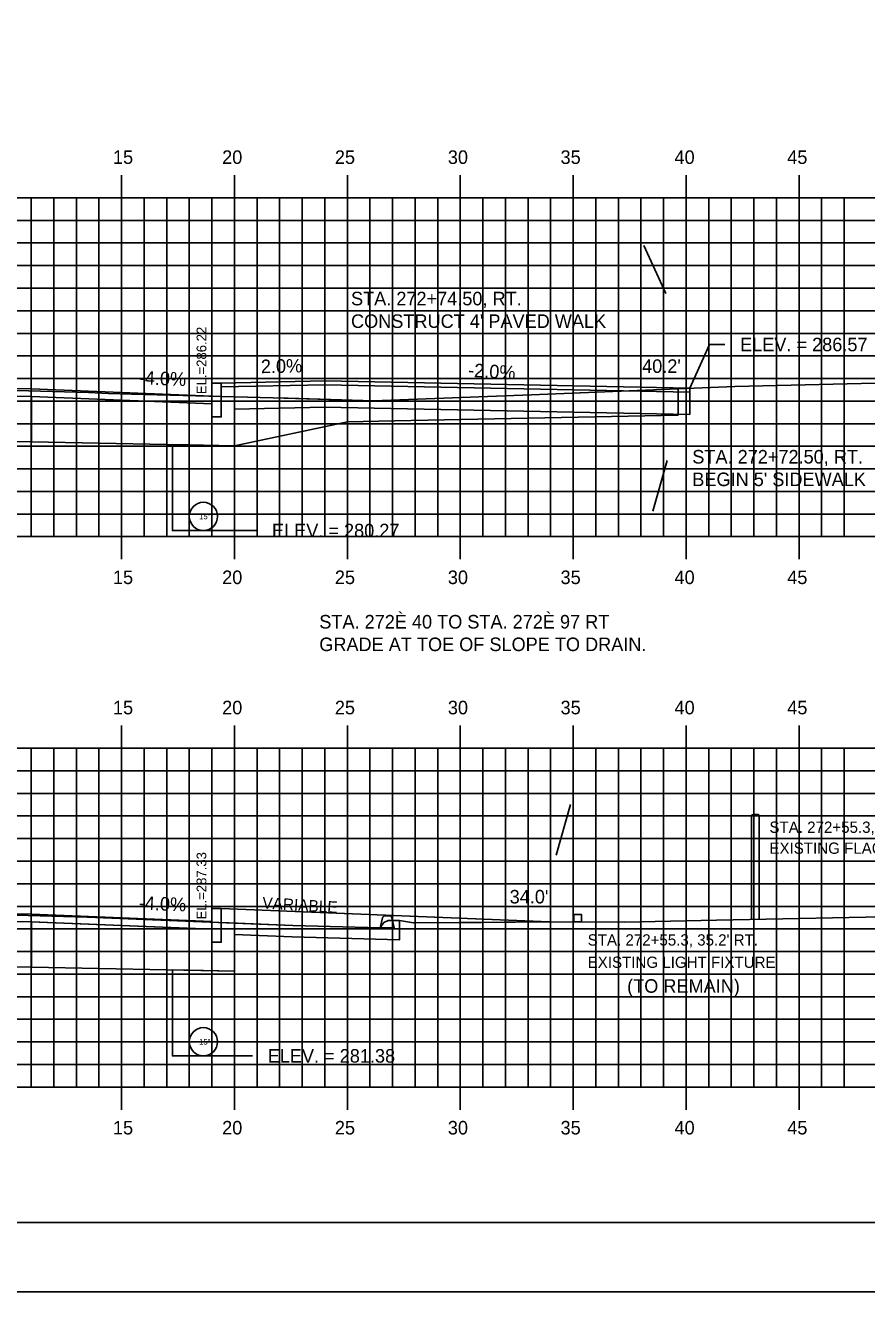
# Model space of a CAD drawing. Extents: x 852672 to 852842, y 366268 to 366378.
# Drawn here: x 852765.8 to 852803.1, y 366268.2 to 366324.2 of the extents above; entities that cross this region are included whole.
import ezdxf

# ---------------------------------------------------------------- set-up
doc = ezdxf.new("R2010")
doc.units = 0
for name, color, linetype in [('ANNOTATION', 7, 'Continuous'), ('BORDER', 7, 'Continuous'), ('D_Curb_Type1_Rt', 7, 'Continuous'), ('D_Drainage_Text', 7, 'Continuous'), ('D_Roadway_Edge_Shoulder', 7, 'Continuous'), ('D_Roadway_FinishedGrade', 7, 'Continuous'), ('D_Roadway_Sidewalks_Paved', 7, 'Continuous'), ('D_Roadway_SubGrade', 7, 'Continuous'), ('D_Text_Monospaced', 7, 'Continuous'), ('D_Text_Standard', 7, 'Continuous'), ('H_V ANNOTATION', 7, 'Continuous'), ('JUNK COM EXC', 7, 'Continuous'), ('JUNK FILL', 7, 'Continuous'), ('junk grubnfill', 7, 'Continuous'), ('junk strct exc', 7, 'Continuous'), ('MAJOR', 7, 'Continuous'), ('MINOR', 7, 'Continuous'), ('PDRAIN', 7, 'Continuous'), ('PLOT BOUNDARY', 7, 'Continuous'), ('S_Curb_Type_3', 7, 'Continuous'), ('S_Roadway_Centerline', 7, 'Continuous'), ('S_Utilities_Pole_Joint', 7, 'Continuous')]:
    doc.layers.add(name, color=color, linetype=linetype)

msp = doc.modelspace()

# ---------------------------------------------------------------- linework, layer by layer
at = {"layer": 'ANNOTATION'}
for p, q in [((852794.196, 366312.37), (852793.228, 366314.496)), ((852793.617, 366302.727), (852794.26, 366304.973)), ((852789.339, 366287.505), (852789.982, 366289.751))]:
    msp.add_line(p, q, dxfattribs=at)
at = {"layer": 'BORDER'}
msp.add_line((852680.097, 366271.236), (852840.097, 366271.236), dxfattribs=at)
at = {"layer": 'D_Curb_Type1_Rt'}
for points in [[(852774.513, 366308.402), (852774.513, 366306.902), (852774.096, 366306.902), (852774.096, 366308.402)], [(852774.513, 366285.146), (852774.513, 366283.646), (852774.096, 366283.646), (852774.096, 366285.146)]]:
    msp.add_lwpolyline(points, close=True, dxfattribs=at)
at = {"layer": 'D_Roadway_Edge_Shoulder'}
for p, q in [((852766.096, 366308.139), (852774.096, 366307.819)), ((852766.096, 366284.883), (852774.096, 366284.563)), ((852766.083, 366284.55), (852774.096, 366284.23))]:
    msp.add_line(p, q, dxfattribs=at)
for points in [[(852744.096, 366308.139), (852755.096, 366308.359), (852766.096, 366308.139)], [(852744.096, 366284.883), (852755.096, 366285.103), (852766.096, 366284.883)]]:
    msp.add_lwpolyline(points, dxfattribs=at)
at = {"layer": 'D_Roadway_FinishedGrade'}
msp.add_lwpolyline([(852774.513, 366285.146), (852789.054, 366284.547)], dxfattribs=at)
at = {"layer": 'D_Roadway_Sidewalks_Paved'}
for p, q in [((852779.101, 366308.494), (852795.259, 366308.171)), ((852779.101, 366308.327), (852795.259, 366308.004))]:
    msp.add_line(p, q, dxfattribs=at)
msp.add_lwpolyline([(852774.513, 366308.402), (852779.101, 366308.494), (852779.101, 366308.328), (852774.513, 366308.236)], close=True, dxfattribs=at)
at = {"layer": 'D_Roadway_SubGrade'}
for p, q in [((852795.259, 366308.171), (852795.259, 366307.004)), ((852774.096, 366307.486), (852774.096, 366307.819)), ((852779.078, 366307.327), (852795.259, 366307.004)), ((852782.399, 366284.612), (852782.399, 366283.753))]:
    msp.add_line(p, q, dxfattribs=at)
for points in [[(852744.103, 366305.806), (852744.103, 366307.806), (852755.103, 366308.026), (852766.103, 366307.806), (852766.103, 366305.806), (852755.103, 366306.026)], [(852744.103, 366282.55), (852744.103, 366284.55), (852755.103, 366284.77), (852766.103, 366284.55), (852766.103, 366282.55), (852755.103, 366282.77)]]:
    msp.add_lwpolyline(points, close=True, dxfattribs=at)
for points in [[(852774.513, 366308.236), (852779.101, 366308.328), (852779.101, 366307.328), (852775.096, 366307.247), (852775.096, 366305.626)], [(852775.096, 366305.625), (852766.103, 366305.806), (852766.103, 366307.806), (852774.096, 366307.486)], [(852775.096, 366285.122), (852775.096, 366282.37)], [(852775.096, 366282.37), (852766.103, 366282.55), (852766.103, 366284.55), (852774.096, 366284.23)], [(852775.096, 366283.995), (852777.657, 366283.893), (852782.399, 366283.753)]]:
    msp.add_lwpolyline(points, dxfattribs=at)
at = {"layer": 'D_Text_Standard'}
for points in [[(852795.259, 366308.171), (852796.127, 366310.109), (852796.807, 366310.109)], [(852775.096, 366301.872), (852775.398, 366301.872), (852776.078, 366301.872)], [(852775.096, 366278.616), (852775.207, 366278.616), (852775.887, 366278.616)]]:
    msp.add_lwpolyline(points, dxfattribs=at)
at = {"layer": 'JUNK COM EXC'}
for points in [[(852735.096, 366307.276), (852735.096, 366305.626), (852744.103, 366305.806), (852755.103, 366306.026), (852766.103, 366305.806), (852775.096, 366305.625), (852775.096, 366307.795), (852770.534, 366307.914), (852769.515, 366307.943), (852768.631, 366307.978), (852755.835, 366308.343), (852755.304, 366308.357), (852743.535, 366308.037), (852743.147, 366308.03), (852742.933, 366308.015), (852737.092, 366307.564)], [(852794.74, 366308.149), (852788.243, 366307.882), (852781.253, 366307.615), (852777.468, 366307.73), (852776.806, 366307.75), (852775.096, 366307.795), (852775.096, 366305.625), (852780.096, 366306.689), (852782.176, 366306.731), (852794.74, 366306.982)], [(852735.096, 366284.093), (852735.096, 366282.37), (852744.103, 366282.55), (852755.103, 366282.77), (852766.103, 366282.55), (852775.096, 366282.37), (852775.096, 366284.495), (852768.567, 366284.754), (852760.727, 366284.977), (852755.337, 366285.113), (852750.296, 366284.984), (852743.148, 366284.793), (852739.613, 366284.517), (852736.872, 366284.298), (852735.862, 366284.203)]]:
    msp.add_lwpolyline(points, close=True, dxfattribs=at)
at = {"layer": 'JUNK FILL'}
msp.add_lwpolyline([(852774.513, 366284.518), (852777.674, 366284.393), (852781.547, 366284.279), (852781.713, 366284.526), (852781.906, 366284.604), (852782.399, 366284.612), (852783.022, 366284.502), (852786.038, 366284.524), (852789.054, 366284.547), (852781.784, 366284.847), (852774.513, 366285.146)], close=True, dxfattribs=at)
at = {"layer": 'junk grubnfill'}
msp.add_lwpolyline([(852775.096, 366284.495), (852775.096, 366283.995), (852777.657, 366283.893), (852782.399, 366283.753), (852782.399, 366284.612), (852781.906, 366284.604), (852781.713, 366284.526), (852781.547, 366284.279), (852777.674, 366284.393), (852775.096, 366284.495)], dxfattribs=at)
at = {"layer": 'junk strct exc'}
for points in [[(852772.346, 366305.682), (852772.346, 366301.872), (852775.096, 366301.872), (852775.096, 366305.627)], [(852772.346, 366282.426), (852772.346, 366278.616), (852775.096, 366278.616), (852775.096, 366282.371)]]:
    msp.add_lwpolyline(points, close=True, dxfattribs=at)
at = {"layer": 'MAJOR'}
for p, q in [((852770.096, 366317.604), (852770.096, 366316.602)), ((852775.096, 366317.604), (852775.096, 366316.602)), ((852780.096, 366317.604), (852780.096, 366316.602)), ((852785.096, 366317.604), (852785.096, 366316.602)), ((852790.096, 366317.604), (852790.096, 366316.602)), ((852795.096, 366317.604), (852795.096, 366316.602)), ((852800.096, 366317.604), (852800.096, 366316.602)), ((852685.096, 366316.602), (852825.096, 366316.602)), ((852685.096, 366316.602), (852825.096, 366316.602)), ((852770.096, 366301.602), (852770.096, 366316.602)), ((852775.096, 366301.602), (852775.096, 366316.602)), ((852780.096, 366301.602), (852780.096, 366316.602)), ((852785.096, 366301.602), (852785.096, 366316.602)), ((852790.096, 366301.602), (852790.096, 366316.602)), ((852795.096, 366301.602), (852795.096, 366316.602)), ((852800.096, 366301.602), (852800.096, 366316.602)), ((852685.096, 366311.602), (852825.096, 366311.602)), ((852685.096, 366306.602), (852825.096, 366306.602)), ((852685.096, 366301.602), (852825.096, 366301.602)), ((852685.096, 366301.602), (852825.096, 366301.602)), ((852770.096, 366300.6), (852770.096, 366301.602)), ((852775.096, 366300.6), (852775.096, 366301.602)), ((852780.096, 366300.6), (852780.096, 366301.602)), ((852785.096, 366300.6), (852785.096, 366301.602)), ((852790.096, 366300.6), (852790.096, 366301.602)), ((852795.096, 366300.6), (852795.096, 366301.602)), ((852800.096, 366300.6), (852800.096, 366301.602)), ((852770.096, 366293.238), (852770.096, 366292.236)), ((852775.096, 366293.238), (852775.096, 366292.236)), ((852780.096, 366293.238), (852780.096, 366292.236)), ((852785.096, 366293.238), (852785.096, 366292.236)), ((852790.096, 366293.238), (852790.096, 366292.236)), ((852795.096, 366293.238), (852795.096, 366292.236)), ((852800.096, 366293.238), (852800.096, 366292.236)), ((852685.096, 366292.236), (852825.096, 366292.236)), ((852685.096, 366292.236), (852825.096, 366292.236)), ((852770.096, 366277.236), (852770.096, 366292.236)), ((852775.096, 366277.236), (852775.096, 366292.236)), ((852780.096, 366277.236), (852780.096, 366292.236)), ((852785.096, 366277.236), (852785.096, 366292.236)), ((852790.096, 366277.236), (852790.096, 366292.236)), ((852795.096, 366277.236), (852795.096, 366292.236)), ((852800.096, 366277.236), (852800.096, 366292.236)), ((852685.096, 366287.236), (852825.096, 366287.236)), ((852685.096, 366282.236), (852825.096, 366282.236)), ((852685.096, 366277.236), (852825.096, 366277.236)), ((852770.096, 366276.234), (852770.096, 366277.236)), ((852775.096, 366276.234), (852775.096, 366277.236)), ((852780.096, 366276.234), (852780.096, 366277.236)), ((852785.096, 366276.234), (852785.096, 366277.236)), ((852790.096, 366276.234), (852790.096, 366277.236)), ((852795.096, 366276.234), (852795.096, 366277.236)), ((852800.096, 366276.234), (852800.096, 366277.236))]:
    msp.add_line(p, q, dxfattribs=at)
at = {"layer": 'MINOR'}
for p, q in [((852766.096, 366301.602), (852766.096, 366316.602)), ((852767.096, 366301.602), (852767.096, 366316.602)), ((852768.096, 366301.602), (852768.096, 366316.602)), ((852769.096, 366301.602), (852769.096, 366316.602)), ((852771.096, 366301.602), (852771.096, 366316.602)), ((852772.096, 366301.602), (852772.096, 366316.602)), ((852773.096, 366301.602), (852773.096, 366316.602)), ((852774.096, 366301.602), (852774.096, 366316.602)), ((852776.096, 366301.602), (852776.096, 366316.602)), ((852777.096, 366301.602), (852777.096, 366316.602)), ((852778.096, 366301.602), (852778.096, 366316.602)), ((852779.096, 366301.602), (852779.096, 366316.602)), ((852781.096, 366301.602), (852781.096, 366316.602)), ((852782.096, 366301.602), (852782.096, 366316.602)), ((852783.096, 366301.602), (852783.096, 366316.602)), ((852784.096, 366301.602), (852784.096, 366316.602)), ((852786.096, 366301.602), (852786.096, 366316.602)), ((852787.096, 366301.602), (852787.096, 366316.602)), ((852788.096, 366301.602), (852788.096, 366316.602)), ((852789.096, 366301.602), (852789.096, 366316.602)), ((852791.096, 366301.602), (852791.096, 366316.602)), ((852792.096, 366301.602), (852792.096, 366316.602)), ((852793.096, 366301.602), (852793.096, 366316.602)), ((852794.096, 366301.602), (852794.096, 366316.602)), ((852796.096, 366301.602), (852796.096, 366316.602)), ((852797.096, 366301.602), (852797.096, 366316.602)), ((852798.096, 366301.602), (852798.096, 366316.602)), ((852799.096, 366301.602), (852799.096, 366316.602)), ((852801.096, 366301.602), (852801.096, 366316.602)), ((852802.096, 366301.602), (852802.096, 366316.602)), ((852685.096, 366315.602), (852825.096, 366315.602)), ((852685.096, 366314.602), (852825.096, 366314.602)), ((852685.096, 366313.602), (852825.096, 366313.602)), ((852685.096, 366312.602), (852825.096, 366312.602)), ((852685.096, 366310.602), (852825.096, 366310.602)), ((852685.096, 366309.602), (852825.096, 366309.602)), ((852685.096, 366308.602), (852825.096, 366308.602)), ((852685.096, 366307.602), (852825.096, 366307.602)), ((852685.096, 366305.602), (852825.096, 366305.602)), ((852685.096, 366304.602), (852825.096, 366304.602)), ((852685.096, 366303.602), (852825.096, 366303.602)), ((852685.096, 366302.602), (852825.096, 366302.602)), ((852766.096, 366277.236), (852766.096, 366292.236)), ((852767.096, 366277.236), (852767.096, 366292.236)), ((852768.096, 366277.236), (852768.096, 366292.236)), ((852769.096, 366277.236), (852769.096, 366292.236)), ((852771.096, 366277.236), (852771.096, 366292.236)), ((852772.096, 366277.236), (852772.096, 366292.236)), ((852773.096, 366277.236), (852773.096, 366292.236)), ((852774.096, 366277.236), (852774.096, 366292.236)), ((852776.096, 366277.236), (852776.096, 366292.236)), ((852777.096, 366277.236), (852777.096, 366292.236)), ((852778.096, 366277.236), (852778.096, 366292.236)), ((852779.096, 366277.236), (852779.096, 366292.236)), ((852781.096, 366277.236), (852781.096, 366292.236)), ((852782.096, 366277.236), (852782.096, 366292.236)), ((852783.096, 366277.236), (852783.096, 366292.236)), ((852784.096, 366277.236), (852784.096, 366292.236)), ((852786.096, 366277.236), (852786.096, 366292.236)), ((852787.096, 366277.236), (852787.096, 366292.236)), ((852788.096, 366277.236), (852788.096, 366292.236)), ((852789.096, 366277.236), (852789.096, 366292.236)), ((852791.096, 366277.236), (852791.096, 366292.236)), ((852792.096, 366277.236), (852792.096, 366292.236)), ((852793.096, 366277.236), (852793.096, 366292.236)), ((852794.096, 366277.236), (852794.096, 366292.236)), ((852796.096, 366277.236), (852796.096, 366292.236)), ((852797.096, 366277.236), (852797.096, 366292.236)), ((852798.096, 366277.236), (852798.096, 366292.236)), ((852799.096, 366277.236), (852799.096, 366292.236)), ((852801.096, 366277.236), (852801.096, 366292.236)), ((852802.096, 366277.236), (852802.096, 366292.236)), ((852685.096, 366291.236), (852825.096, 366291.236)), ((852685.096, 366290.236), (852825.096, 366290.236)), ((852685.096, 366289.236), (852825.096, 366289.236)), ((852685.096, 366288.236), (852825.096, 366288.236)), ((852685.096, 366286.236), (852825.096, 366286.236)), ((852685.096, 366285.236), (852825.096, 366285.236)), ((852685.096, 366284.236), (852825.096, 366284.236)), ((852685.096, 366283.236), (852825.096, 366283.236)), ((852685.096, 366281.236), (852825.096, 366281.236)), ((852685.096, 366280.236), (852825.096, 366280.236)), ((852685.096, 366279.236), (852825.096, 366279.236)), ((852685.096, 366278.236), (852825.096, 366278.236))]:
    msp.add_line(p, q, dxfattribs=at)
at = {"layer": 'PDRAIN'}
for points in [[(852772.346, 366305.681), (852772.346, 366301.872), (852775.096, 366301.872), (852775.096, 366305.625)], [(852772.346, 366282.425), (852772.346, 366278.616), (852775.096, 366278.616), (852775.096, 366282.37)]]:
    msp.add_lwpolyline(points, dxfattribs=at)
for centre in [(852773.721, 366302.497), (852773.721, 366279.241)]:
    msp.add_circle(centre, 0.625, dxfattribs=at)
at = {"layer": 'PLOT BOUNDARY'}
msp.add_lwpolyline([(852672.003, 366268.177), (852842.003, 366268.177), (852842.003, 366378.177), (852672.003, 366378.177)], close=True, dxfattribs=at)
at = {"layer": 'S_Curb_Type_3'}
for points in [[(852782.069, 366284.723), (852782.172, 366284.279), (852781.547, 366284.279), (852781.65, 366284.723)], [(852781.771, 366284.82), (852781.947, 366284.82)]]:
    msp.add_lwpolyline(points, dxfattribs=at)
for centre, start, end in [((852781.771, 366284.695), 90, 167.0054), ((852781.947, 366284.695), 12.9946, 90)]:
    msp.add_arc(centre, 0.125, start, end, dxfattribs=at)
at = {"layer": 'S_Roadway_Centerline'}
for points in [[(852728.866, 366307.44), (852729.91, 366307.44), (852730.784, 366307.475), (852730.859, 366307.473), (852734.112, 366307.134), (852734.197, 366307.146), (852737.092, 366307.564), (852742.933, 366308.015), (852743.147, 366308.03), (852743.535, 366308.037), (852755.304, 366308.357), (852755.835, 366308.343), (852768.631, 366307.978), (852769.515, 366307.943), (852770.534, 366307.914), (852776.806, 366307.75), (852781.253, 366307.615), (852788.243, 366307.882), (852797.252, 366308.252), (852804.718, 366308.433), (852813.271, 366308.593), (852814.799, 366308.574), (852816.079, 366308.529)], [(852724.924, 366284.328), (852730.5, 366284.261), (852732.107, 366284.155), (852734.099, 366283.95), (852735.862, 366284.203), (852736.872, 366284.298), (852739.613, 366284.517), (852743.148, 366284.793), (852750.296, 366284.984), (852755.337, 366285.113), (852760.727, 366284.977), (852768.567, 366284.754), (852777.674, 366284.393), (852781.547, 366284.279), (852781.713, 366284.526), (852781.906, 366284.604), (852782.399, 366284.612), (852783.022, 366284.502), (852789.054, 366284.547), (852792.363, 366284.537), (852796.447, 366284.629), (852805.26, 366284.798)]]:
    msp.add_lwpolyline(points, dxfattribs=at)
at = {"layer": 'S_Utilities_Pole_Joint'}
for p, q in [((852797.996, 366284.659), (852797.993, 366289.279)), ((852798.329, 366284.659), (852798.326, 366289.279))]:
    msp.add_line(p, q, dxfattribs=at)
msp.add_lwpolyline([(852790.13, 366284.882), (852790.13, 366284.549), (852790.463, 366284.549), (852790.463, 366284.882)], close=True, dxfattribs=at)
for centre, radius, start, end in [((852798.124, 366288.926), 0.376, 79.8458, 110.3714), ((852798.076, 366289.39), 0.139, 233.1708, 306.9106), ((852798.243, 366289.168), 0.139, 53.1708, 126.9106)]:
    msp.add_arc(centre, radius, start, end, dxfattribs=at)

# ---------------------------------------------------------------- texts
at = {"layer": 'ANNOTATION'}
for s, p in [('STA. 272+74.50, RT.', (852780.257, 366311.842)), ("CONSTRUCT 4' PAVED WALK", (852780.257, 366310.842)), ('STA. 272+72.50, RT.', (852795.371, 366304.839)), ("BEGIN 5' SIDEWALK", (852795.371, 366303.839)), ('(TO REMAIN)', (852792.485, 366281.409))]:
    msp.add_text(s, height=0.6, dxfattribs=at).set_placement(p)
for s, rotation, p in [('2.0%', 1.1481, (852776.271, 366308.837)), ('-2.0%', 356.4987, (852785.429, 366308.683)), ('-4.0%', 357.7074, (852770.85, 366308.35)), ('-4.0%', 357.7074, (852770.85, 366285.094))]:
    msp.add_text(s, height=0.6, rotation=rotation, dxfattribs=at).set_placement(p)
at = {"layer": 'D_Drainage_Text'}
for s, p in [('STA. 272È 40 TO STA. 272È 97 RT', (852778.852, 366297.535)), ('GRADE AT TOE OF SLOPE TO DRAIN.', (852778.852, 366296.535))]:
    msp.add_text(s, height=0.6, dxfattribs=at).set_placement(p)
at = {"layer": 'D_Text_Monospaced'}
for s, p in [("STA. 272+55.3, 42.9' RT.", (852798.786, 366288.489)), ('EXISTING FLAG POLE', (852798.786, 366287.561)), ("STA. 272+55.3, 35.2' RT.", (852790.737, 366283.499)), ('EXISTING LIGHT FIXTURE', (852790.737, 366282.51))]:
    msp.add_text(s, height=0.49998, dxfattribs=at).set_placement(p)
at = {"layer": 'D_Text_Standard'}
for s, height, rotation, p in [(' EL.=286.22', 0.4335, 90, (852773.851, 366307.75)), (' EL.=287.33', 0.4335, 90, (852773.851, 366284.494)), ('VARIABLE', 0.51, 356.4969, (852776.318, 366285.141))]:
    msp.add_text(s, height=height, rotation=rotation, dxfattribs=at).set_placement(p)
for s, p in [('ELEV. = 286.57', (852797.487, 366309.809)), ("40.2'", (852793.148, 366308.851)), ('ELEV. = 280.27', (852776.758, 366301.572)), ("34.0'", (852787.282, 366285.363)), ('ELEV. = 281.38', (852776.567, 366278.316))]:
    msp.add_text(s, height=0.6, dxfattribs=at).set_placement(p)
at = {"layer": 'H_V ANNOTATION'}
for s, p in [('15', (852769.714, 366318.102)), ('20', (852774.55, 366318.102)), ('25', (852779.542, 366318.102)), ('30', (852784.545, 366318.102)), ('35', (852789.537, 366318.102)), ('40', (852794.583, 366318.102)), ('45', (852799.575, 366318.102)), ('15', (852769.714, 366299.502)), ('20', (852774.55, 366299.502)), ('25', (852779.542, 366299.502)), ('30', (852784.545, 366299.502)), ('35', (852789.537, 366299.502)), ('40', (852794.583, 366299.502)), ('45', (852799.575, 366299.502)), ('15', (852769.714, 366293.736)), ('20', (852774.55, 366293.736)), ('25', (852779.542, 366293.736)), ('30', (852784.545, 366293.736)), ('35', (852789.537, 366293.736)), ('40', (852794.583, 366293.736)), ('45', (852799.575, 366293.736)), ('15', (852769.714, 366275.136)), ('20', (852774.55, 366275.136)), ('25', (852779.542, 366275.136)), ('30', (852784.545, 366275.136)), ('35', (852789.537, 366275.136)), ('40', (852794.583, 366275.136)), ('45', (852799.575, 366275.136))]:
    msp.add_text(s, height=0.6, dxfattribs=at).set_placement(p)
at = {"layer": 'PDRAIN'}
for p in [(852773.534, 366302.372), (852773.534, 366279.116)]:
    msp.add_text('15"', height=0.25, dxfattribs=at).set_placement(p)

doc.saveas('drawing.dxf')
